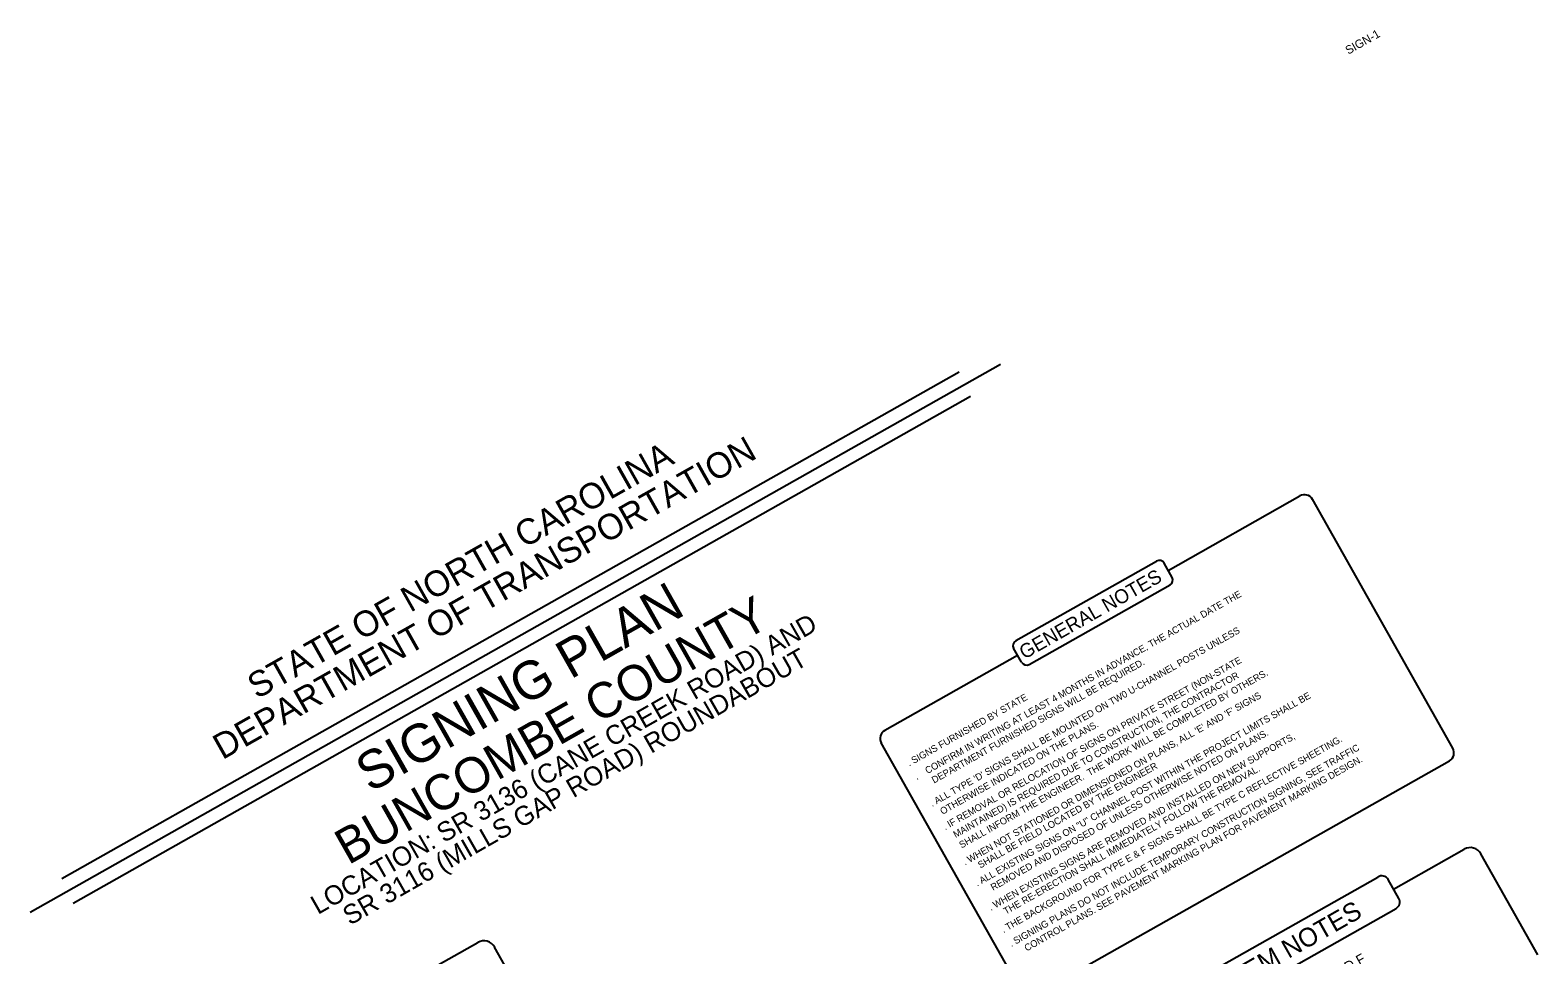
# Model space of a CAD drawing. Extents: x 2217708 to 2219063, y 217550 to 219141.
# Drawn here: x 2217790 to 2218884, y 218471 to 219141 of the extents above; entities that cross this region are included whole.
import ezdxf

# ---------------------------------------------------------------- set-up
doc = ezdxf.new("R2010")
doc.units = 0
for name, color, linetype in [('Default', 7, 'Continuous'), ('Prop Text', 7, 'Continuous'), ('Sheet Title CELL', 7, 'Continuous')]:
    doc.layers.add(name, color=color, linetype=linetype)

msp = doc.modelspace()

# ---------------------------------------------------------------- linework, layer by layer
at = {"layer": 'Default'}
for points in [[(2217790.3, 218501.8), (2218494.1, 218899.2)], [(2217813.3, 218526), (2218464.3, 218893.6)], [(2217821.4, 218508.2), (2218472.4, 218875.8)]]:
    msp.add_lwpolyline(points, dxfattribs=at)
at = {"layer": 'Sheet Title CELL'}
for p, q in [((2218615.8, 218749.6), (2218711.4, 218803.6)), ((2218822.3, 218620.6), (2218720.5, 218801.1)), ((2218618.7, 218744.5), (2218612.9, 218754.7)), ((2218410.2, 218633.6), (2218506.6, 218688)), ((2218509.5, 218682.9), (2218503.7, 218693.2)), ((2218509.6, 218444), (2218407.7, 218624.5)), ((2218517.9, 218441), (2218819.8, 218611.5)), ((2218779.3, 218518.4), (2218830.5, 218547.4)), ((2218884, 218470.7), (2218842.6, 218544)), ((2218783.1, 218511.6), (2218775.4, 218525.3)), ((2218059.7, 218448.5), (2218115.1, 218479.8)), ((2218218.7, 218314.4), (2218127.2, 218476.4))]:
    msp.add_line(p, q, dxfattribs=at)
for points in [[(2218505.2, 218698.6), (2218607.4, 218756.3)], [(2218515, 218681.4), (2218617.2, 218739)], [(2218611.6, 218438.8), (2218767.8, 218527.1)], [(2218625, 218416.1), (2218781.1, 218504.4)]]:
    msp.add_lwpolyline(points, dxfattribs=at)
for centre, radius, start, end in [((2218714.7, 218797.8), 6.68, 29.4569, 119.4569), ((2218609.4, 218752.8), 4.01, 29.4569, 119.4569), ((2218615.2, 218742.5), 4.01, 299.4569, 29.4569), ((2218507.2, 218695.1), 4.01, 119.4569, 209.4569), ((2218513, 218684.9), 4.01, 209.4569, 299.4569), ((2218413.5, 218627.7), 6.68, 119.4569, 209.4569), ((2218816.5, 218617.3), 6.68, 299.4569, 29.4569), ((2218834.9, 218539.6), 8.91, 29.4569, 119.4569), ((2218770.8, 218522.7), 5.34, 29.4569, 123.7349), ((2218778.5, 218509), 5.34, 299.4569, 29.4569), ((2218119.5, 218472), 8.91, 29.4569, 119.4569)]:
    msp.add_arc(centre, radius, start, end, dxfattribs=at)

# ---------------------------------------------------------------- texts
at = {"layer": 'Default'}
for s, height, rotation, p in [('DEPARTMENT OF TRANSPORTATION', 18.494, 29.4569, (2217929.8, 218611.9)), ('STATE OF NORTH CAROLINA', 18.494, 29.4569, (2217954.8, 218655.9)), ('SIGNING PLAN', 27.74, 29.5143, (2218037, 218588)), ('GENERAL NOTES', 10.196, 29.6392, (2218511.5, 218684.8)), ('BUNCOMBE COUNTY', 25.685, 29.5409, (2218021.1, 218535.6)), ('CONFIRM IN WRITING AT LEAST 4 MONTHS IN ADVANCE, THE ACTUAL DATE THE', 4.979, 29.4835, (2218441.2, 218601.8)), ('LOCATION: SR 3136 (CANE CREEK ROAD) AND', 13.87, 29.6966, (2217999, 218499.6)), (". ALL TYPE 'D' SIGNS SHALL BE MOUNTED ON TW0 U-CHANNEL POSTS UNLESS", 4.979, 29.4835, (2218444.6, 218578)), ('SR 3116 (MILLS GAP ROAD) ROUNDABOUT', 13.87, 29.6966, (2218022.2, 218491.8)), ('. IF REMOVAL OR RELOCATION OF SIGNS ON PRIVATE STREET (NON-STATE ', 4.979, 29.4835, (2218454.1, 218561.1)), ('DEPARTMENT FURNISHED SIGNS WILL BE REQUIRED.', 4.979, 29.4835, (2218446, 218594.9)), ('  MAINTAINED) IS REQUIRED DUE TO CONSTRUCTION, THE CONTRACTOR ', 4.979, 29.4835, (2218458.4, 218553.6)), ('  SHALL INFORM THE ENGINEER.  THE WORK WILL BE COMPLETED BY OTHERS.', 4.979, 29.4835, (2218462.7, 218546)), ('. SIGNS FURNISHED BY STATE ', 4.979, 29.4835, (2218428, 218607.3)), (". WHEN NOT STATIONED OR DIMENSIONED ON PLANS, ALL 'E' AND 'F' SIGNS ", 4.979, 29.4835, (2218468.5, 218535.6)), ('. ALL EXISTING SIGNS ON "U" CHANNEL POST WITHIN THE PROJECT LIMITS SHALL BE', 4.979, 29.4835, (2218477.3, 218520.2)), ('  OTHERWISE INDICATED ON THE PLANS.', 4.979, 29.4835, (2218448.9, 218570.4)), ('REMOVED AND DISPOSED OF UNLESS OTHERWISE NOTED ON PLANS.', 4.979, 29.4835, (2218488.8, 218517.1)), ('. WHEN EXISTING SIGNS ARE REMOVED AND INSTALLED ON NEW SUPPORTS, ', 4.979, 29.4835, (2218487.2, 218502.6)), ('. THE BACKGROUND FOR TYPE E & F SIGNS SHALL BE TYPE C REFLECTIVE SHEETING. ', 4.979, 29.4835, (2218496.3, 218486.5)), ('. SIGNING PLANS DO NOT INCLUDE TEMPORARY CONSTRUCTION SIGNING, SEE TRAFFIC', 4.979, 29.4835, (2218502, 218476.4)), ('SHALL BE FIELD LOCATED BY THE ENGINEER', 4.979, 29.4835, (2218479.5, 218533.3)), ('CONTROL PLANS. SEE PAVEMENT MARKING PLAN FOR PAVEMENT MARKING DESIGN.', 4.979, 29.4835, (2218513.2, 218473.1)), ('. ', 4.98, 29.4835, (2218433.5, 218597.5)), ('THE RE-ERECTION SHALL IMMEDIATELY FOLLOW THE REMOVAL.', 4.979, 29.4835, (2218498.1, 218499.8))]:
    msp.add_text(s, height=height, rotation=rotation, dxfattribs=at).set_placement(p)
at = {"layer": 'Prop Text'}
msp.add_text('SIGN-1', height=6.11, rotation=29.4785, dxfattribs=at).set_placement((2218746.5, 219123.5))
at = {"layer": 'Sheet Title CELL'}
for s, height, rotation, p in [('PAY ITEM NOTES', 13.591, 29.6392, (2218625, 218423.3)), ('SIGN ERECTION, TYPE D, E, AND F', 7.199, 29.4835, (2218618.6, 218386.1))]:
    msp.add_text(s, height=height, rotation=rotation, dxfattribs=at).set_placement(p)

doc.saveas('drawing.dxf')
